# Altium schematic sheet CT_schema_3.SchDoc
size 314 x 170 mm
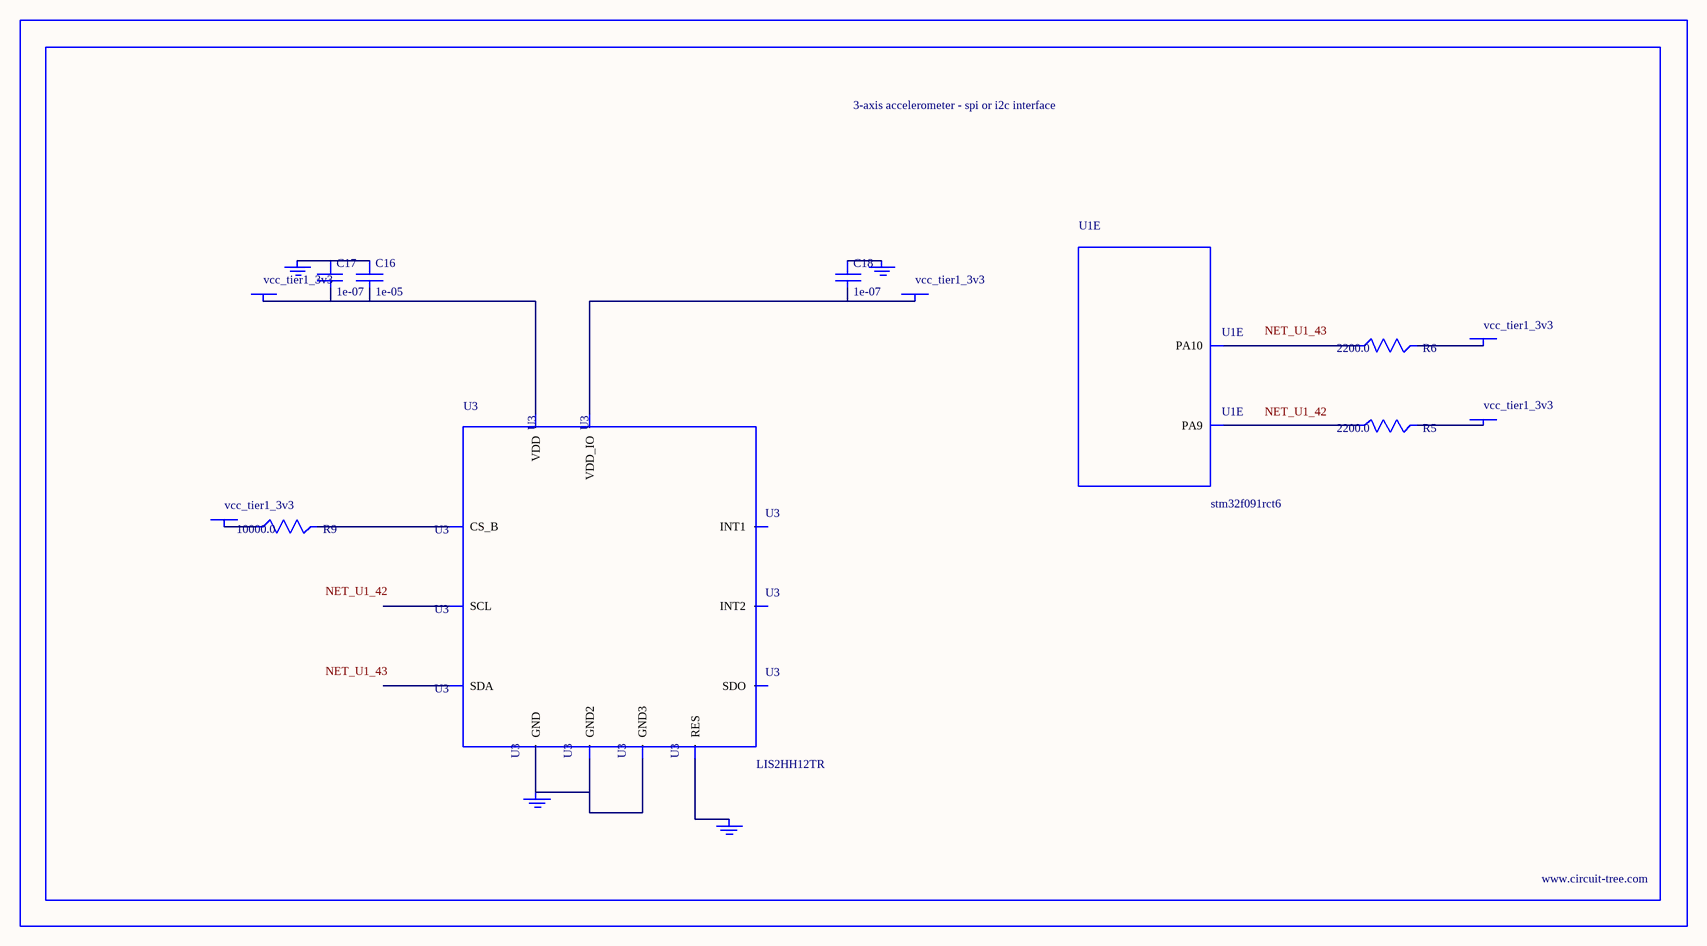
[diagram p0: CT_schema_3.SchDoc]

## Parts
BORDER2  (no value)
C16  1e-05  [C0805]
C17  1e-07  [C0402]
C18  1e-07  [C0402]
GND_INSTANCE_2_0  (no value)
GND_INSTANCE_2_1  (no value)
GND_INSTANCE_2_2  (no value)
GND_INSTANCE_2_3  (no value)
POWER_INSTANCE_2_0  vcc_tier1_3v3
POWER_INSTANCE_2_1  vcc_tier1_3v3
POWER_INSTANCE_2_2  vcc_tier1_3v3
POWER_INSTANCE_2_3  vcc_tier1_3v3
POWER_INSTANCE_2_4  vcc_tier1_3v3
R5  2200.0  [R0603]
R6  2200.0  [R0603]
R9  10000.0  [R0603]
U1  stm32f091rct6  [LQFP64]  (part E of 7)
U3  LIS2HH12TR  [LGA-12]

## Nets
NetC16_1: C16.1 C17.1 GND_INSTANCE_2_1.0(GND)
NetC16_2: C16.2 C17.2 POWER_INSTANCE_2_1.0(PWR) U3.9(VDD)
NetC18_1: C18.1 GND_INSTANCE_2_2.0(GND)
NetC18_2: C18.2 POWER_INSTANCE_2_2.0(PWR) U3.10(VDD_IO)
NetGND_INSTANCE_2_0_0: GND_INSTANCE_2_0.0(GND) U3.5(RES)
NetGND_INSTANCE_2_3_0: GND_INSTANCE_2_3.0(GND) U3.6(GND) U3.7(GND2) U3.8(GND3)
NetPOWER_INSTANCE_2_0_0: POWER_INSTANCE_2_0.0(PWR) R9.1
NetPOWER_INSTANCE_2_3_0: POWER_INSTANCE_2_3.0(PWR) R5.2
NetPOWER_INSTANCE_2_4_0: POWER_INSTANCE_2_4.0(PWR) R6.2
NetR5_1: R5.1 U1.42(PA9)
NetR6_1: R6.1 U1.43(PA10)
NetR9_2: R9.2 U3.2(CS_B)

Not connected (* = marked no-connect by the designer): U3 1(SCL) 3(SDO) 4(SDA) 11(INT2) 12(INT1)

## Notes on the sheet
- Labels drawn without touching a wire or pin: NET_U1_42, NET_U1_43

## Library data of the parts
BORDER2 = BORDER_PAGE2
C16 = C0805C106K8RACTU
C17 C18 = C0402C104K3RACTU
GND_INSTANCE_2_0-GND_INSTANCE_2_3 = GND
POWER_INSTANCE_2_0-POWER_INSTANCE_2_4 = PWR
R5 R6 = RC0603JR-072K2L
R9 = RC0603JR-0710KL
